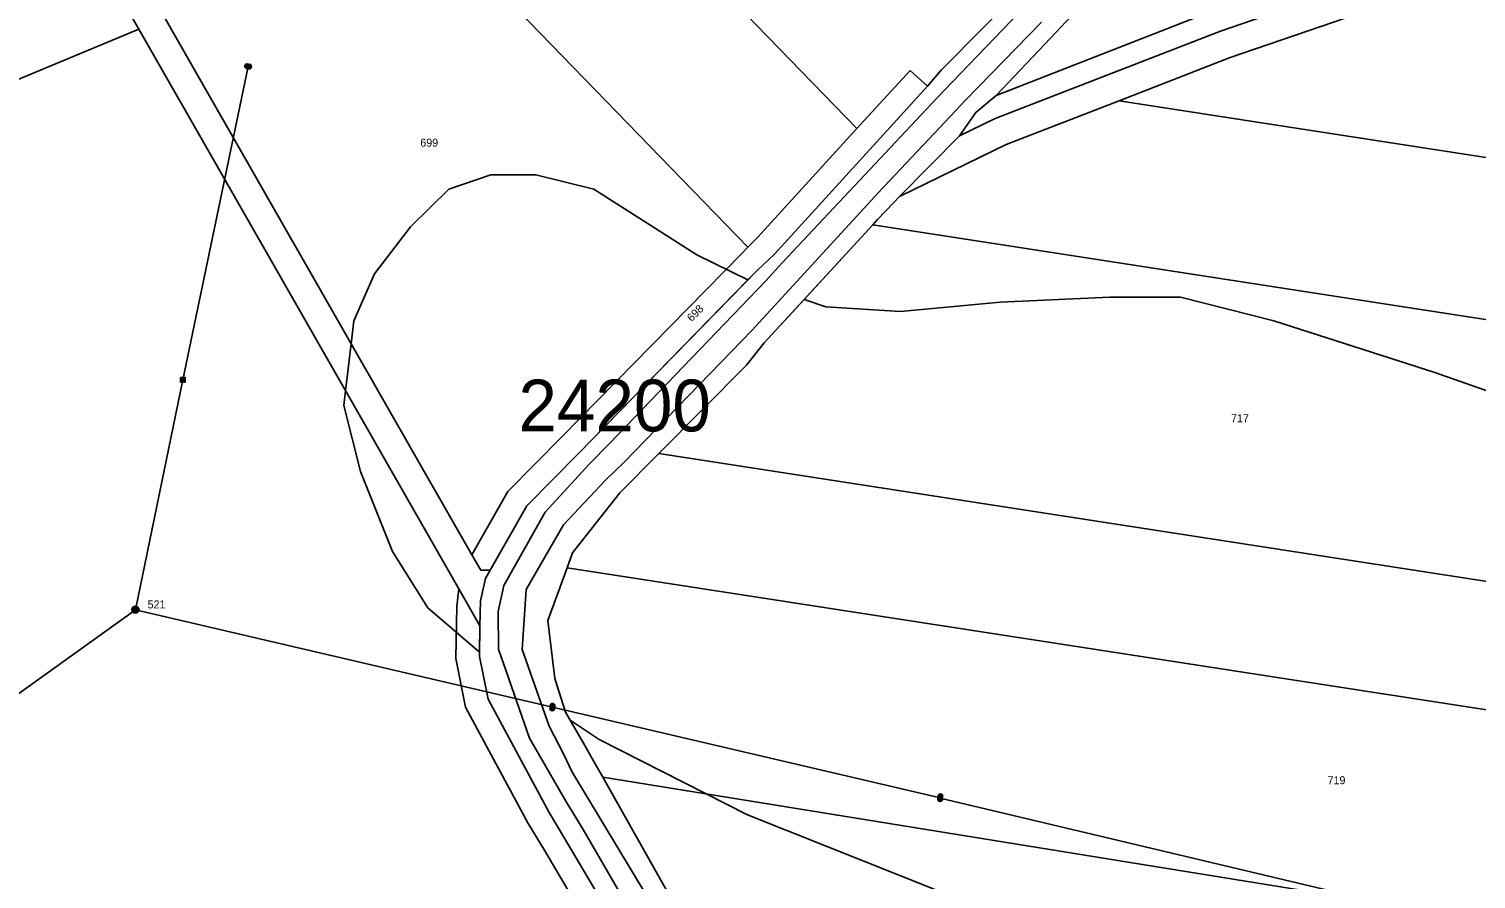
# Model space of a CAD drawing. Extents: x -725765 to -723182, y -1052705 to -1049154.
# Drawn here: x -724492.6 to -724185, y -1050562.6 to -1050382 of the extents above; entities that cross this region are included whole.
import ezdxf

# ---------------------------------------------------------------- set-up
doc = ezdxf.new("R2010")
doc.units = 0
for name, color, linetype in [('Vrstva 1', 7, 'Continuous'), ('Vrstva 12', 7, 'Continuous'), ('Vrstva 17', 7, 'Continuous'), ('Vrstva 18', 7, 'Continuous'), ('Vrstva 25', 7, 'Continuous'), ('Vrstva 4', 7, 'Continuous'), ('Vrstva 52', 7, 'Continuous'), ('Vrstva 53', 7, 'Continuous')]:
    doc.layers.add(name, color=color, linetype=linetype)

msp = doc.modelspace()

# ---------------------------------------------------------------- linework, layer by layer
at = {"layer": 'Vrstva 1'}
for points in [[(-724432.88, -1050283.35), (-724316.62, -1050403.16)], [(-724458.1, -1050306.38), (-724339.76, -1050428.35)], [(-724398.43, -1050493.7), (-724489.27, -1050334.85)], [(-724469.21, -1050382.02), (-724494.68, -1050337.48)], [(-724275.49, -1050383.94), (-724253.22, -1050360.22)], [(-724200.38, -1050368.99), (-724239.36, -1050382.43)], [(-724298.73, -1050390.73), (-724280.28, -1050372.09)], [(-724198.73, -1050374.77), (-724237.3, -1050388.06)], [(-724287.04, -1050396.14), (-724238.42, -1050377.1)], [(-724469.21, -1050382.02), (-724714.83, -1050484.41)], [(-724401.18, -1050500.98), (-724469.21, -1050382.02)], [(-724239.36, -1050382.43), (-724287.26, -1050401.01)], [(-724287.04, -1050396.14), (-724275.49, -1050383.94)], [(-724316.62, -1050403.16), (-724305.32, -1050390.77)], [(-724305.32, -1050390.77), (-724301.63, -1050394.14)], [(-724301.63, -1050394.14), (-724298.73, -1050390.73)], [(-724237.3, -1050388.06), (-724260.86, -1050397.21)], [(-724334.14, -1050429.8), (-724301.63, -1050394.14)], [(-724287.04, -1050396.14), (-724291.32, -1050399.7)], [(-724294.84, -1050404.69), (-724291.32, -1050399.7)], [(-724260.86, -1050397.21), (-724284.86, -1050406.51)], [(-724260.86, -1050397.21), (-724039.37, -1050431.45)], [(-724337.71, -1050426.3), (-724316.62, -1050403.16)], [(-724287.26, -1050401.01), (-724294.84, -1050404.69)], [(-724294.84, -1050404.69), (-724307.58, -1050417.59)], [(-724284.86, -1050406.51), (-724307.58, -1050417.59)], [(-724307.58, -1050417.59), (-724308.86, -1050418.89)], [(-724308.86, -1050418.89), (-724312.25, -1050422.47)], [(-724313.26, -1050423.57), (-724336.29, -1050448.69)], [(-724312.25, -1050422.47), (-724313.26, -1050423.57)], [(-724313.26, -1050423.57), (-724042.29, -1050465.46)], [(-724339.76, -1050428.35), (-724337.71, -1050426.3)], [(-724379.34, -1050468.68), (-724341.02, -1050429.61)], [(-724341.02, -1050429.61), (-724339.76, -1050428.35)], [(-724337.75, -1050433.22), (-724334.14, -1050429.8)], [(-724375.77, -1050472.18), (-724337.75, -1050433.22)], [(-724336.29, -1050448.69), (-724340.06, -1050453.44)], [(-724358.7, -1050472.21), (-724340.06, -1050453.44)], [(-724390.77, -1050480.24), (-724379.34, -1050468.68)], [(-724386.75, -1050483.29), (-724375.77, -1050472.18)], [(-724367.01, -1050480.59), (-724358.7, -1050472.21)], [(-724358.7, -1050472.21), (-724047, -1050520.4)], [(-724398.43, -1050493.7), (-724390.77, -1050480.24)], [(-724377.08, -1050493.34), (-724367.01, -1050480.59)], [(-724394.56, -1050497), (-724386.75, -1050483.29)], [(-724396.54, -1050497), (-724398.43, -1050493.7)], [(-724378.21, -1050496.47), (-724377.08, -1050493.34)], [(-724396.54, -1050497), (-724394.56, -1050497)], [(-724395.55, -1050498.74), (-724394.56, -1050497)], [(-724382.28, -1050507.67), (-724378.21, -1050496.47)], [(-724378.21, -1050496.47), (-724049.31, -1050547.31)], [(-724401.64, -1050504.61), (-724401.18, -1050500.98)], [(-724401.18, -1050500.98), (-724396.71, -1050508.8)], [(-724395.55, -1050498.74), (-724396.62, -1050503.49)], [(-724401.83, -1050515.78), (-724401.64, -1050504.61)], [(-724396.71, -1050508.8), (-724396.62, -1050503.49)], [(-724380.83, -1050519.99), (-724382.28, -1050507.67)], [(-724396.82, -1050515.33), (-724396.71, -1050508.8)], [(-724399.76, -1050526.14), (-724401.83, -1050515.78)], [(-724395, -1050524.43), (-724396.82, -1050515.33)], [(-724378.55, -1050527.18), (-724380.83, -1050519.99)], [(-724399.76, -1050526.14), (-724386.44, -1050550.84)], [(-724395, -1050524.43), (-724382.04, -1050548.47)], [(-724374.69, -1050533.76), (-724378.55, -1050527.18)], [(-724372.77, -1050537.16), (-724374.69, -1050533.76)], [(-724370.62, -1050540.98), (-724372.77, -1050537.16)], [(-724339.98, -1050595.36), (-724370.62, -1050540.98)], [(-724370.62, -1050540.98), (-724195.07, -1050569.42)], [(-724386.44, -1050550.84), (-724382.95, -1050556.66)], [(-724382.04, -1050548.47), (-724378.66, -1050554.1)], [(-724382.95, -1050556.66), (-724367.52, -1050582.69)], [(-724378.66, -1050554.1), (-724350.54, -1050601.52)]]:
    msp.add_lwpolyline(points, dxfattribs=at)
at = {"layer": 'Vrstva 12'}
for points in [[(-724445.99, -1050389.92), (-724459.82, -1050456.53)], [(-724445.77, -1050389.97), (-724446.2, -1050389.88)], [(-724459.82, -1050456.53), (-724469.91, -1050505.39)], [(-724469.91, -1050505.39), (-724518.86, -1050540.51)], [(-724381.31, -1050526.09), (-724469.91, -1050505.39)], [(-724381.34, -1050526.36), (-724381.28, -1050525.82)], [(-724298.9, -1050545.35), (-724381.31, -1050526.09)], [(-724298.93, -1050545.65), (-724298.86, -1050545.06)], [(-724298.9, -1050545.46), (-724207.63, -1050567.14)]]:
    msp.add_lwpolyline(points, dxfattribs=at)
at = {"layer": 'Vrstva 25'}
for points in [[(-724460.32, -1050456.03), (-724459.32, -1050456.03), (-724459.32, -1050457.03), (-724460.32, -1050457.03), (-724460.32, -1050456.03)], [(-724460.12, -1050456.23), (-724459.52, -1050456.23), (-724459.52, -1050456.83), (-724460.12, -1050456.83), (-724460.12, -1050456.23)], [(-724459.92, -1050456.43), (-724459.72, -1050456.43), (-724459.72, -1050456.63), (-724459.92, -1050456.63), (-724459.92, -1050456.43)], [(-724470.41, -1050504.89), (-724469.41, -1050504.89), (-724469.41, -1050505.89), (-724470.41, -1050505.89), (-724470.41, -1050504.89)], [(-724470.21, -1050505.09), (-724469.61, -1050505.09), (-724469.61, -1050505.69), (-724470.21, -1050505.69), (-724470.21, -1050505.09)], [(-724470.01, -1050505.29), (-724469.81, -1050505.29), (-724469.81, -1050505.49), (-724470.01, -1050505.49), (-724470.01, -1050505.29)]]:
    msp.add_lwpolyline(points, dxfattribs=at)
for centre, radius in [((-724446.2, -1050389.88), 0.5), ((-724446.2, -1050389.88), 0.3), ((-724446.2, -1050389.88), 0.15), ((-724445.77, -1050389.97), 0.5), ((-724445.77, -1050389.97), 0.3), ((-724445.77, -1050389.97), 0.15), ((-724469.91, -1050505.39), 0.75), ((-724469.91, -1050505.39), 0.032), ((-724381.34, -1050526.36), 0.5), ((-724381.28, -1050525.82), 0.5), ((-724381.34, -1050526.36), 0.3), ((-724381.28, -1050525.82), 0.3), ((-724381.34, -1050526.36), 0.15), ((-724381.28, -1050525.82), 0.15), ((-724298.86, -1050545.06), 0.5), ((-724298.93, -1050545.65), 0.5), ((-724298.93, -1050545.65), 0.3), ((-724298.86, -1050545.06), 0.3), ((-724298.93, -1050545.65), 0.15), ((-724298.86, -1050545.06), 0.15)]:
    msp.add_circle(centre, radius, dxfattribs=at)
at = {"layer": 'Vrstva 4'}
for points in [[(-724296.43, -1050393.36), (-724278.39, -1050374.48)], [(-724293.47, -1050397), (-724277.41, -1050380.5)], [(-724299.6, -1050396.65), (-724296.43, -1050393.36)], [(-724332.48, -1050431.69), (-724299.6, -1050396.65)], [(-724298.97, -1050402.89), (-724293.47, -1050397)], [(-724312.1, -1050416.78), (-724298.97, -1050402.89)], [(-724315.13, -1050420.12), (-724312.1, -1050416.78)], [(-724338.94, -1050446.07), (-724315.13, -1050420.12)], [(-724335.93, -1050435.53), (-724332.48, -1050431.69)], [(-724369.18, -1050470.07), (-724335.93, -1050435.53)], [(-724343.25, -1050450.54), (-724338.94, -1050446.07)], [(-724366.14, -1050474.08), (-724343.25, -1050450.54)], [(-724369.18, -1050470.07), (-724373.4, -1050474.36)], [(-724373.4, -1050474.36), (-724382.84, -1050484.67)], [(-724370.01, -1050477.87), (-724366.14, -1050474.08)], [(-724378.97, -1050487.34), (-724370.01, -1050477.87)], [(-724382.84, -1050484.67), (-724391.62, -1050500.27)], [(-724386.89, -1050501.07), (-724378.97, -1050487.34)], [(-724391.62, -1050500.27), (-724392.83, -1050505.81)], [(-724387.72, -1050513.83), (-724386.89, -1050501.07)], [(-724392.74, -1050513.81), (-724392.83, -1050505.81)], [(-724386.16, -1050532.69), (-724392.74, -1050513.81)], [(-724382.03, -1050530.17), (-724387.72, -1050513.83)], [(-724378.88, -1050536.19), (-724382.03, -1050530.17)], [(-724386.16, -1050532.69), (-724378.44, -1050546.11)], [(-724377.16, -1050539.79), (-724378.88, -1050536.19)], [(-724345.42, -1050592.57), (-724377.16, -1050539.79)], [(-724378.44, -1050546.11), (-724374.79, -1050552.08)], [(-724374.79, -1050552.08), (-724350.49, -1050594.08)]]:
    msp.add_lwpolyline(points, dxfattribs=at)
at = {"layer": 'Vrstva 52'}
for points in [[(-724339.77, -1050435.29), (-724337.75, -1050433.22), (-724334.14, -1050429.8), (-724301.63, -1050394.14), (-724298.73, -1050390.73), (-724280.28, -1050372.09), (-724277.34, -1050368.99), (-724266.18, -1050357.22), (-724261.43, -1050352.21), (-724255.71, -1050344.76), (-724252, -1050339.7), (-724244.58, -1050330.2), (-724227.62, -1050302.53), (-724225.05, -1050297.43), (-724189.41, -1050243.89), (-724175.06, -1050221.03), (-724171.33, -1050214.68), (-724154.83, -1050186.77), (-724131.55, -1050146.44), (-724106.74, -1050102.28), (-724083.12, -1050061.36), (-724078.91, -1050054.34)], [(-724327.83, -1050439.46), (-724313.26, -1050423.57), (-724312.25, -1050422.47), (-724308.86, -1050418.89), (-724307.58, -1050417.59), (-724294.84, -1050404.69), (-724291.32, -1050399.7), (-724287.04, -1050396.14), (-724275.49, -1050383.94), (-724253.22, -1050360.22), (-724234.33, -1050337.94), (-724219.02, -1050314.94), (-724178.5, -1050249.28), (-724166.93, -1050230.48), (-724164.1, -1050225.63), (-724146.89, -1050196.26), (-724117.05, -1050145.72), (-724115.12, -1050142.36), (-724094.14, -1050107.53), (-724069.82, -1050065.37), (-724063.97, -1050054.46)], [(-724339.77, -1050435.29), (-724350.63, -1050430), (-724372.5, -1050416), (-724384.81, -1050413), (-724394.38, -1050413), (-724403.31, -1050416), (-724411.5, -1050424), (-724419.13, -1050434), (-724423.5, -1050444), (-724424.07, -1050448.86), (-724425.26, -1050458.88), (-724425.63, -1050462), (-724422.13, -1050476), (-724415.31, -1050493), (-724407.81, -1050505), (-724396.8, -1050514.39)], [(-724396.8, -1050514.39), (-724396.71, -1050508.8), (-724396.62, -1050503.49), (-724395.55, -1050498.74), (-724394.56, -1050497), (-724386.75, -1050483.29), (-724375.77, -1050472.18), (-724339.77, -1050435.29)], [(-724377.55, -1050528.88), (-724378.55, -1050527.18), (-724380.83, -1050519.99), (-724382.28, -1050507.67), (-724378.21, -1050496.47), (-724377.08, -1050493.34), (-724367.01, -1050480.59), (-724358.7, -1050472.21), (-724340.06, -1050453.44), (-724336.29, -1050448.69), (-724327.83, -1050439.46)], [(-724327.83, -1050439.46), (-724323.19, -1050441), (-724307.38, -1050442), (-724286.19, -1050440), (-724262.88, -1050439), (-724247.88, -1050439), (-724228, -1050444), (-724193.81, -1050455), (-724159.5, -1050467)], [(-724501.6, -1050700.47), (-724492.01, -1050709.38), (-724469.18, -1050731.12), (-724448.78, -1050742.99), (-724438.67, -1050747.5), (-724431.76, -1050749.69), (-724418.61, -1050752.86), (-724393.4, -1050759.99), (-724375.97, -1050762.12), (-724347.98, -1050763.49), (-724322.7, -1050762.83), (-724311.82, -1050765.44), (-724293.06, -1050765.94), (-724275.87, -1050751.85), (-724277.01, -1050740.4), (-724286.94, -1050716.83), (-724304.57, -1050683.26), (-724325.45, -1050643.39), (-724350.54, -1050601.52), (-724378.66, -1050554.1), (-724382.04, -1050548.47), (-724395, -1050524.43), (-724396.82, -1050515.33), (-724396.8, -1050514.39)], [(-724169.81, -1050673), (-724191, -1050655), (-724203.38, -1050635), (-724221.81, -1050607), (-724230.81, -1050597), (-724243.13, -1050590), (-724259.5, -1050581), (-724307.13, -1050562), (-724339.88, -1050549), (-724371.38, -1050533), (-724377.55, -1050528.88)], [(-724377.55, -1050528.88), (-724374.69, -1050533.76), (-724372.77, -1050537.16), (-724370.62, -1050540.98), (-724339.98, -1050595.36)]]:
    msp.add_lwpolyline(points, dxfattribs=at)

# ---------------------------------------------------------------- texts
at = {"layer": 'Vrstva 17'}
msp.add_text('521 ', height=1.7, dxfattribs=at).set_placement((-724467.34, -1050505.12))
at = {"layer": 'Vrstva 18'}
for s, p in [('699', (-724409.39, -1050406.99)), ('717', (-724237.11, -1050465.56)), ('719', (-724216.6, -1050542.49))]:
    msp.add_text(s, height=1.7, dxfattribs=at).set_placement(p)
msp.add_text('698', height=1.7, rotation=45.0004, dxfattribs=at).set_placement((-724351.72, -1050444.29))
at = {"layer": 'Vrstva 53'}
msp.add_text('24200', height=11, dxfattribs=at).set_placement((-724388.54, -1050467.5))

doc.saveas('drawing.dxf')
